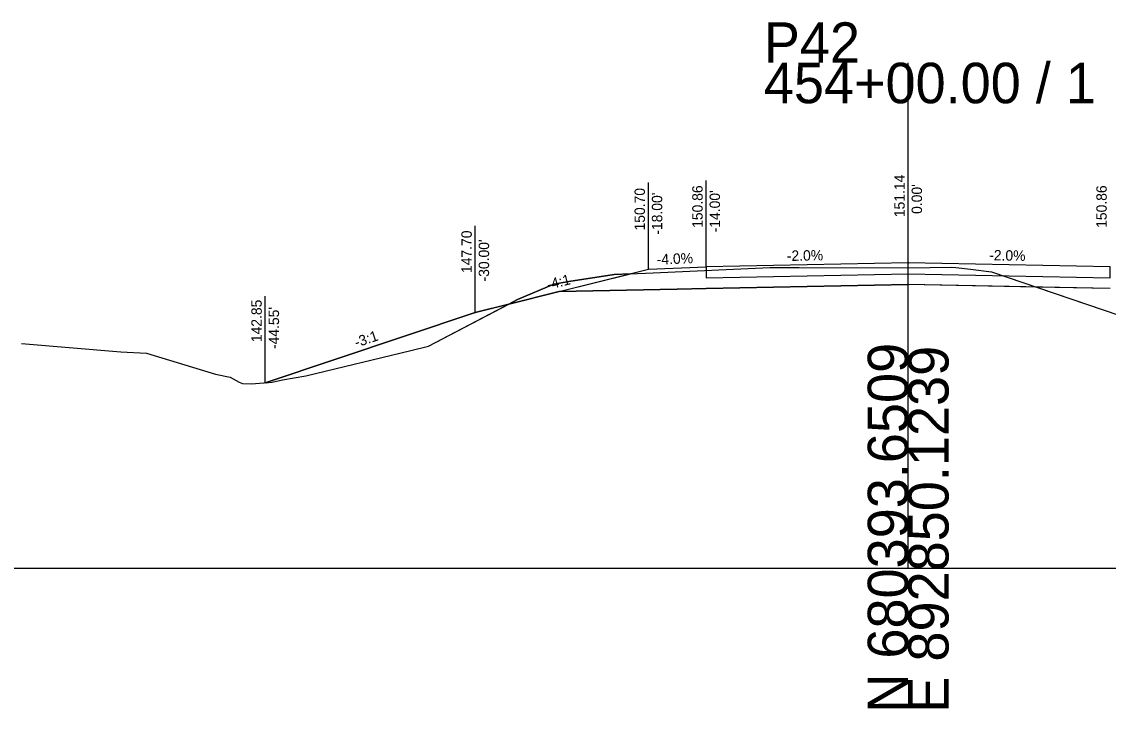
# Model space of a CAD drawing. Extents: x -26 to 4403, y -13 to 9578.
# Drawn here: x 188.6 to 263.9, y 3490.3 to 3537.8 of the extents above; entities that cross this region are included whole.
import ezdxf

# ---------------------------------------------------------------- set-up
doc = ezdxf.new("R2010")
doc.units = 0
for name, color, linetype in [('_CIVIL_CONSTRUCTION', 7, 'Continuous'), ('CONST_DCH', 7, 'Continuous'), ('CONST_LV3', 7, 'Continuous'), ('DTM_CORRIDOR', 7, 'Continuous'), ('DTM_TEMP_DROP', 7, 'Continuous'), ('DTM_X_GROUND', 7, 'Continuous'), ('SLOPE_STAKES_FILL', 7, 'Continuous'), ('XS_CELL', 7, 'Continuous'), ('XS_M_SHAPES_EARTHWORK', 7, 'Continuous'), ('XS_P_ASPHALT', 7, 'Continuous'), ('XS_P_GROUND', 7, 'Continuous'), ('XS_P_SHOULDER', 7, 'Continuous'), ('XS_P_SUBGRADE_GRANULAR', 7, 'Continuous'), ('XS_P_TX_CLEARZONE', 7, 'Continuous'), ('XS_P_TX_FS_BS', 7, 'Continuous')]:
    doc.layers.add(name, color=color, linetype=linetype)

msp = doc.modelspace()

# ---------------------------------------------------------------- linework, layer by layer
at = {"layer": 'CONST_LV3'}
msp.add_lwpolyline([(220, 3517.701), (225.826, 3519.158), (225.826, 3519.158)], dxfattribs=at)
at = {"layer": 'DTM_X_GROUND'}
msp.add_lwpolyline([(188.569, 3515.567), (195.438, 3514.986), (197.216, 3514.901), (201.992, 3513.449), (203.01, 3513.227), (203.638, 3512.879), (203.875, 3512.788), (204.469, 3512.775), (205.923, 3512.888), (206.654, 3513.036), (208.252, 3513.332), (215.536, 3515.069), (216.76, 3515.385), (222.929, 3518.6), (225.452, 3519.677), (226.483, 3519.853), (229.624, 3520.342), (232.328, 3520.454), (240.446, 3520.825), (242.449, 3520.836), (250.002, 3520.811), (250.026, 3520.811), (253.025, 3520.845), (253.314, 3520.82), (254.313, 3520.72), (255.766, 3520.524), (264.68, 3517.505)], dxfattribs=at)
at = {"layer": 'XS_CELL'}
for p, q in [((250, 3500), (250, 3535)), ((0, 3500), (250, 3500)), ((250, 3500), (400, 3500))]:
    msp.add_line(p, q, dxfattribs=at)
at = {"layer": 'XS_M_SHAPES_EARTHWORK'}
for points in [[(222.317, 3518.281), (222.929, 3518.6), (225.452, 3519.677), (226.483, 3519.853), (229.624, 3520.342), (232.328, 3520.454), (240.446, 3520.825), (242.449, 3520.836), (250.002, 3520.811), (250.026, 3520.811), (253.025, 3520.845), (253.314, 3520.82), (254.313, 3520.72), (255.766, 3520.524), (258.897, 3519.464), (250, 3519.641), (236, 3519.361), (234, 3519.321), (225.826, 3519.158)], [(205.446, 3512.851), (205.923, 3512.888), (206.654, 3513.036), (208.252, 3513.332), (215.536, 3515.069), (216.76, 3515.385), (222.317, 3518.281), (220, 3517.701)]]:
    msp.add_lwpolyline(points, close=True, dxfattribs=at)
msp.add_lwpolyline([(264, 3519.361), (258.897, 3519.464), (264.68, 3517.505)], dxfattribs=at)
at = {"layer": 'XS_P_ASPHALT'}
msp.add_lwpolyline([(250, 3521.141), (236, 3520.861), (236, 3520.861), (236, 3520.111), (250, 3520.391), (250, 3520.391), (250, 3520.391), (264, 3520.111), (264, 3520.861), (264, 3520.861), (250, 3521.141), (250, 3521.141), (250, 3521.141)], dxfattribs=at)
at = {"layer": 'XS_P_GROUND'}
msp.add_line((230.748, 3520.388), (229.624, 3520.342), dxfattribs=at)
for points in [[(205.446, 3512.851), (220, 3517.701), (220, 3517.701), (232, 3520.701), (232, 3520.701)], [(222.317, 3518.281), (225.826, 3519.158), (230.748, 3520.388)], [(229.624, 3520.342), (226.483, 3519.853), (225.452, 3519.677), (222.929, 3518.6), (222.317, 3518.281)]]:
    msp.add_lwpolyline(points, dxfattribs=at)
at = {"layer": 'XS_P_SHOULDER'}
msp.add_lwpolyline([(232, 3520.701), (236, 3520.861), (236, 3520.861)], dxfattribs=at)
at = {"layer": 'XS_P_SUBGRADE_GRANULAR'}
for points in [[(225.826, 3519.158), (234, 3519.321), (234, 3519.321), (236, 3519.361), (236, 3519.361)], [(236, 3519.361), (250, 3519.641), (250, 3519.641)], [(264, 3519.361), (250, 3519.641), (250, 3519.641)]]:
    msp.add_lwpolyline(points, dxfattribs=at)
at = {"layer": 'XS_P_TX_CLEARZONE'}
for p, q in [((236, 3520.861), (236, 3526.861)), ((236, 3520.861), (236, 3526.861)), ((236, 3520.861), (236, 3526.861)), ((250, 3521.141), (250, 3527.141)), ((250, 3521.141), (250, 3527.141)), ((250, 3521.141), (250, 3527.141)), ((250, 3521.141), (250, 3527.141)), ((250, 3521.141), (250, 3527.141)), ((250, 3521.141), (250, 3527.141)), ((232, 3520.701), (232, 3526.701)), ((232, 3520.701), (232, 3526.701)), ((232, 3520.701), (232, 3526.701)), ((232, 3520.701), (232, 3526.701)), ((232, 3520.701), (232, 3526.701)), ((232, 3520.701), (232, 3526.701)), ((220, 3517.701), (220, 3523.701)), ((220, 3517.701), (220, 3523.701)), ((220, 3517.701), (220, 3523.701)), ((220, 3517.701), (220, 3523.701)), ((220, 3517.701), (220, 3523.701)), ((220, 3517.701), (220, 3523.701)), ((205.446, 3512.851), (205.446, 3518.851)), ((205.446, 3512.851), (205.446, 3518.851)), ((205.446, 3512.851), (205.446, 3518.851)), ((205.446, 3512.851), (205.446, 3518.851)), ((205.446, 3512.851), (205.446, 3518.851)), ((205.446, 3512.851), (205.446, 3518.851))]:
    msp.add_line(p, q, dxfattribs=at)

# ---------------------------------------------------------------- texts
at = {"layer": '_CIVIL_CONSTRUCTION'}
for p in [(235.961, 3520.801), (249.961, 3521.081)]:
    msp.add_text('X', height=0.12, dxfattribs=at).set_placement(p)
at = {"layer": 'CONST_DCH'}
msp.add_text('X', height=0.12, dxfattribs=at).set_placement((205.407, 3512.791))
at = {"layer": 'DTM_CORRIDOR'}
msp.add_text('X', height=0.12, dxfattribs=at).set_placement((205.407, 3512.791))
at = {"layer": 'DTM_TEMP_DROP'}
msp.add_text('X', height=0.12, dxfattribs=at).set_placement((231.961, 3520.641))
at = {"layer": 'SLOPE_STAKES_FILL'}
msp.add_text('X', height=0.12, dxfattribs=at).set_placement((219.961, 3517.641))
at = {"layer": 'XS_CELL'}
for s, p in [('P42', (240, 3535)), ('454+00.00 / 1', (240, 3532.2))]:
    msp.add_text(s, height=2.8, dxfattribs=at).set_placement(p)
for s, p in [('N 680393.6509', (250, 3490)), ('E 892850.1239', (252.8, 3490))]:
    msp.add_text(s, height=2.8, rotation=90, dxfattribs=at).set_placement(p)
at = {"layer": 'XS_P_TX_CLEARZONE'}
for s, p in [('151.14', (249.76, 3524.309)), ('151.14', (249.76, 3524.309)), ('151.14', (249.76, 3524.309)), ('151.14', (249.76, 3524.309)), ('151.14', (249.76, 3524.309)), ('151.14', (249.76, 3524.309)), ('150.70', (231.76, 3523.387)), ('150.70', (231.76, 3523.387)), ('150.70', (231.76, 3523.387)), ('150.70', (231.76, 3523.387)), ('150.70', (231.76, 3523.387)), ('150.70', (231.76, 3523.387)), ('150.86', (235.76, 3523.569)), ('150.86', (235.76, 3523.569)), ('150.86', (235.76, 3523.569)), ("-14.00'", (236.96, 3523.258)), ("-14.00'", (236.96, 3523.258)), ("-14.00'", (236.96, 3523.258)), ("0.00'", (250.96, 3524.535)), ("0.00'", (250.96, 3524.535)), ("0.00'", (250.96, 3524.535)), ("0.00'", (250.96, 3524.535)), ("0.00'", (250.96, 3524.535)), ("0.00'", (250.96, 3524.535)), ('150.86', (263.76, 3523.569)), ('150.86', (263.76, 3523.569)), ('150.86', (263.76, 3523.569)), ('150.86', (263.76, 3523.569)), ('150.86', (263.76, 3523.569)), ('150.86', (263.76, 3523.569)), ("-18.00'", (232.96, 3523.098)), ("-18.00'", (232.96, 3523.098)), ("-18.00'", (232.96, 3523.098)), ("-18.00'", (232.96, 3523.098)), ("-18.00'", (232.96, 3523.098)), ("-18.00'", (232.96, 3523.098)), ('147.70', (219.76, 3520.443)), ('147.70', (219.76, 3520.443)), ('147.70', (219.76, 3520.443)), ('147.70', (219.76, 3520.443)), ('147.70', (219.76, 3520.443)), ('147.70', (219.76, 3520.443)), ("-30.00'", (220.96, 3519.859)), ("-30.00'", (220.96, 3519.859)), ("-30.00'", (220.96, 3519.859)), ("-30.00'", (220.96, 3519.859)), ("-30.00'", (220.96, 3519.859)), ("-30.00'", (220.96, 3519.859)), ('142.85', (205.206, 3515.655)), ('142.85', (205.206, 3515.655)), ('142.85', (205.206, 3515.655)), ('142.85', (205.206, 3515.655)), ('142.85', (205.206, 3515.655)), ('142.85', (205.206, 3515.655)), ("-44.55'", (206.406, 3515.179)), ("-44.55'", (206.406, 3515.179)), ("-44.55'", (206.406, 3515.179)), ("-44.55'", (206.406, 3515.179)), ("-44.55'", (206.406, 3515.179)), ("-44.55'", (206.406, 3515.179))]:
    msp.add_text(s, height=0.72, rotation=90, dxfattribs=at).set_placement(p)
at = {"layer": 'XS_P_TX_FS_BS'}
for s, rotation, p in [('-4.0%', 2.29061, (232.592, 3521.025)), ('-4.0%', 2.29061, (232.592, 3521.025)), ('-4.0%', 2.29061, (232.592, 3521.025)), ('-2.0%', 1.14576, (241.598, 3521.274)), ('-2.0%', 1.14576, (241.598, 3521.274)), ('-2.0%', 1.14576, (241.598, 3521.274)), ('-2.0%', 358.85424, (255.61, 3521.329)), ('-2.0%', 358.85424, (255.61, 3521.329)), ('-2.0%', 358.85424, (255.61, 3521.329)), ('-4:1', 14.03624, (225.047, 3519.273)), ('-4:1', 14.03624, (225.047, 3519.273)), ('-4:1', 14.03624, (225.047, 3519.273)), ('-3:1', 18.43323, (211.768, 3515.274)), ('-3:1', 18.43323, (211.768, 3515.274)), ('-3:1', 18.43323, (211.768, 3515.274))]:
    msp.add_text(s, height=0.72, rotation=rotation, dxfattribs=at).set_placement(p)

doc.saveas('drawing.dxf')
